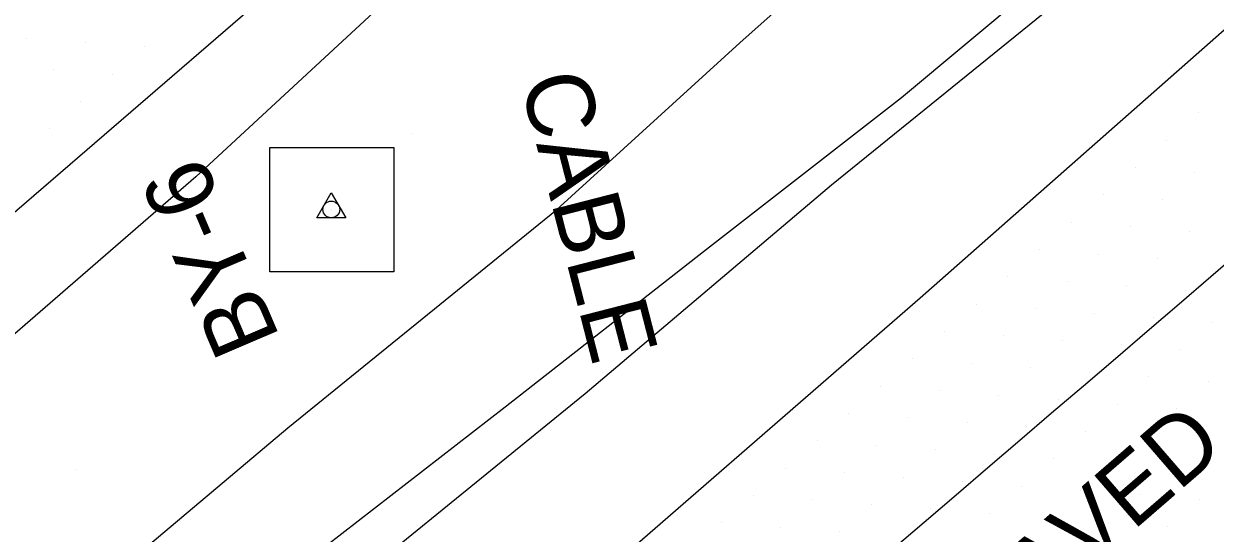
# Model space of a CAD drawing. Extents: x 1548934 to 1561348, y 809680 to 824075.
# Drawn here: x 1551686.9 to 1551757.9, y 810616.2 to 810646.5 of the extents above; entities that cross this region are included whole.
import ezdxf

# ---------------------------------------------------------------- set-up
doc = ezdxf.new("R2010")
doc.units = 0
for name, color, linetype in [('CTL Secondary Horizontal and Vertical Text', 7, 'Continuous'), ('E_NCDOT_Vertical_Profile_Ground_Line', 7, 'Continuous'), ('Exist DTM QL2 LIDAR Elevation Point', 7, 'Continuous'), ('Exist DTM Scan Elevation Point', 7, 'Continuous'), ('Exist Guardrail Cable Guide Rail', 7, 'Continuous'), ('Exist Guardrail Text', 7, 'Continuous'), ('Exist Roads EOP Text', 7, 'Continuous'), ('P_NCDOT_Horizontal_Alignment', 7, 'Continuous'), ('P_NCDOT_Horizontal_Alignment_Tick_Small', 7, 'Continuous'), ('P_RDY_Terminator_Cell', 7, 'Continuous'), ('PH Exist DTM Breakline', 7, 'Continuous')]:
    doc.layers.add(name, color=color, linetype=linetype)

msp = doc.modelspace()

# ---------------------------------------------------------------- linework, layer by layer
at = {"layer": 'E_NCDOT_Vertical_Profile_Ground_Line'}
for points in [[(1551616.71, 810576.292), (1551639.811, 810595.486), (1551662.662, 810614.925), (1551685.424, 810634.556), (1551708.169, 810654.186)], [(1551626.097, 810533.004), (1551648.898, 810552.5), (1551671.875, 810571.791), (1551694.667, 810591.296), (1551717.688, 810610.535), (1551740.33, 810630.215), (1551762.82, 810650.073)]]:
    msp.add_lwpolyline(points, dxfattribs=at)
at = {"layer": 'Exist DTM QL2 LIDAR Elevation Point'}
for p, q in [((1551709.996, 810639.982), (1551709.996, 810639.982)), ((1551699.995, 810629.981), (1551699.995, 810629.981)), ((1551689.994, 810619.98), (1551689.994, 810619.98))]:
    msp.add_line(p, q, dxfattribs=at)
at = {"layer": 'Exist DTM Scan Elevation Point'}
for p, q in [((1551687.025, 810645.703), (1551687.025, 810645.703)), ((1551690.551, 810645.436), (1551690.551, 810645.436)), ((1551694.077, 810645.169), (1551694.077, 810645.169)), ((1551688.655, 810643.807), (1551688.655, 810643.807)), ((1551692.18, 810643.54), (1551692.18, 810643.54)), ((1551690.284, 810641.911), (1551690.284, 810641.911)), ((1551756.933, 810641.237), (1551756.933, 810641.237)), ((1551688.388, 810640.282), (1551688.388, 810640.282)), ((1551755.036, 810639.607), (1551755.036, 810639.607)), ((1551753.139, 810637.978), (1551753.139, 810637.978)), ((1551756.664, 810637.71), (1551756.664, 810637.71)), ((1551751.243, 810636.349), (1551751.243, 810636.349)), ((1551754.768, 810636.081), (1551754.768, 810636.081)), ((1551749.346, 810634.72), (1551749.346, 810634.72)), ((1551752.871, 810634.452), (1551752.871, 810634.452)), ((1551756.396, 810634.184), (1551756.396, 810634.184)), ((1551747.451, 810633.092), (1551747.451, 810633.092)), ((1551750.975, 810632.823), (1551750.975, 810632.823)), ((1551754.5, 810632.555), (1551754.5, 810632.555)), ((1551745.554, 810631.463), (1551745.554, 810631.463)), ((1551749.079, 810631.195), (1551749.079, 810631.195)), ((1551752.603, 810630.927), (1551752.603, 810630.927)), ((1551756.128, 810630.659), (1551756.128, 810630.659)), ((1551743.658, 810629.834), (1551743.658, 810629.834)), ((1551747.183, 810629.566), (1551747.183, 810629.566)), ((1551750.707, 810629.298), (1551750.707, 810629.298)), ((1551754.232, 810629.03), (1551754.232, 810629.03)), ((1551757.757, 810628.762), (1551757.757, 810628.762)), ((1551741.762, 810628.205), (1551741.762, 810628.205)), ((1551745.286, 810627.937), (1551745.286, 810627.937)), ((1551748.811, 810627.669), (1551748.811, 810627.669)), ((1551752.336, 810627.401), (1551752.336, 810627.401)), ((1551755.861, 810627.133), (1551755.861, 810627.133)), ((1551739.865, 810626.576), (1551739.865, 810626.576)), ((1551743.39, 810626.308), (1551743.39, 810626.308)), ((1551746.915, 810626.04), (1551746.915, 810626.04)), ((1551750.439, 810625.772), (1551750.439, 810625.772)), ((1551753.964, 810625.504), (1551753.964, 810625.504)), ((1551737.969, 810624.947), (1551737.969, 810624.947)), ((1551741.494, 810624.679), (1551741.494, 810624.679)), ((1551757.489, 810625.236), (1551757.489, 810625.236)), ((1551745.018, 810624.411), (1551745.018, 810624.411)), ((1551748.543, 810624.143), (1551748.543, 810624.143)), ((1551736.073, 810623.319), (1551736.073, 810623.319)), ((1551752.068, 810623.875), (1551752.068, 810623.875)), ((1551755.593, 810623.607), (1551755.593, 810623.607)), ((1551739.597, 810623.05), (1551739.597, 810623.05)), ((1551743.122, 810622.782), (1551743.122, 810622.782)), ((1551746.647, 810622.514), (1551746.647, 810622.514)), ((1551750.171, 810622.246), (1551750.171, 810622.246)), ((1551753.696, 810621.978), (1551753.696, 810621.978)), ((1551734.176, 810621.69), (1551734.176, 810621.69)), ((1551737.701, 810621.422), (1551737.701, 810621.422)), ((1551741.226, 810621.153), (1551741.226, 810621.153)), ((1551757.222, 810621.711), (1551757.222, 810621.711)), ((1551744.75, 810620.885), (1551744.75, 810620.885)), ((1551748.275, 810620.617), (1551748.275, 810620.617)), ((1551732.28, 810620.061), (1551732.28, 810620.061)), ((1551735.805, 810619.793), (1551735.805, 810619.793)), ((1551751.8, 810620.35), (1551751.8, 810620.35)), ((1551755.325, 810620.082), (1551755.325, 810620.082)), ((1551739.329, 810619.524), (1551739.329, 810619.524)), ((1551742.854, 810619.256), (1551742.854, 810619.256)), ((1551746.379, 810618.988), (1551746.379, 810618.988)), ((1551730.384, 810618.432), (1551730.384, 810618.432)), ((1551749.904, 810618.721), (1551749.904, 810618.721)), ((1551753.429, 810618.453), (1551753.429, 810618.453)), ((1551733.908, 810618.164), (1551733.908, 810618.164)), ((1551737.433, 810617.896), (1551737.433, 810617.896)), ((1551740.958, 810617.628), (1551740.958, 810617.628)), ((1551756.954, 810618.185), (1551756.954, 810618.185)), ((1551744.482, 810617.36), (1551744.482, 810617.36)), ((1551748.007, 810617.092), (1551748.007, 810617.092)), ((1551728.487, 810616.803), (1551728.487, 810616.803)), ((1551732.012, 810616.535), (1551732.012, 810616.535)), ((1551735.536, 810616.267), (1551735.536, 810616.267)), ((1551751.533, 810616.824), (1551751.533, 810616.824)), ((1551755.058, 810616.556), (1551755.058, 810616.556))]:
    msp.add_line(p, q, dxfattribs=at)
at = {"layer": 'Exist Guardrail Cable Guide Rail'}
msp.add_lwpolyline([(1551762.322, 810661.326), (1551750.708, 810651.754), (1551739.198, 810642.126), (1551727.399, 810632.951), (1551715.572, 810623.694), (1551703.898, 810614.617), (1551692.087, 810605.359), (1551680.215, 810595.939), (1551668.418, 810586.655), (1551656.719, 810577.461), (1551645.067, 810568.012), (1551633.432, 810558.34)], dxfattribs=at)
at = {"layer": 'P_NCDOT_Horizontal_Alignment'}
msp.add_line((1551705.209, 810635.48), (1551705.209, 810635.48), dxfattribs=at)
msp.add_line((1551705.209, 810635.48), (1551705.209, 810635.48), dxfattribs=at)
msp.add_lwpolyline([(1551704.343, 810634.98), (1551705.209, 810636.48), (1551706.075, 810634.98)], close=True, dxfattribs=at)
msp.add_lwpolyline([(1551704.343, 810634.98), (1551705.209, 810636.48), (1551706.075, 810634.98)], close=True, dxfattribs=at)
msp.add_circle((1551705.209, 810635.48), 0.5, dxfattribs=at)
msp.add_circle((1551705.209, 810635.48), 0.5, dxfattribs=at)
at = {"layer": 'P_NCDOT_Horizontal_Alignment_Tick_Small'}
msp.add_line((1551705.209, 810635.48), (1551705.209, 810635.48), dxfattribs=at)
msp.add_line((1551705.209, 810635.48), (1551705.209, 810635.48), dxfattribs=at)
msp.add_lwpolyline([(1551701.534, 810639.18), (1551708.946, 810639.18), (1551708.946, 810631.755), (1551701.534, 810631.755)], close=True, dxfattribs=at)
msp.add_lwpolyline([(1551701.534, 810639.18), (1551708.946, 810639.18), (1551708.946, 810631.755), (1551701.534, 810631.755)], close=True, dxfattribs=at)
at = {"layer": 'P_RDY_Terminator_Cell'}
msp.add_lwpolyline([(1551738.663, 810615.215), (1551740.562, 810616.84), (1551742.462, 810618.466), (1551744.361, 810620.092), (1551746.26, 810621.717), (1551748.16, 810623.343), (1551750.059, 810624.968), (1551751.958, 810626.594), (1551753.857, 810628.22), (1551755.757, 810629.845), (1551757.655, 810631.472), (1551759.54, 810633.114)], dxfattribs=at)
at = {"layer": 'PH Exist DTM Breakline'}
for points in [[(1551782.675, 810715.1), (1551773.007, 810705.306), (1551748.224, 810683.207), (1551726.249, 810664.382), (1551697.139, 810637.424), (1551676.304, 810619.385), (1551647.753, 810594.047)], [(1551651.205, 810580.522), (1551687.185, 810609.458), (1551702.625, 810622.447), (1551718.628, 810635.449), (1551729.562, 810645.41), (1551739.115, 810653.932), (1551744.683, 810656.108), (1551750.431, 810659.106), (1551762.96, 810666.985), (1551775.458, 810674.948), (1551786.415, 810682.456), (1551796.394, 810690.846), (1551801.831, 810695.248), (1551805.641, 810698.006)], [(1551653.907, 810568.703), (1551685.171, 810595.198), (1551701.493, 810609.165), (1551720.353, 810624.512), (1551735.042, 810636.95), (1551753.182, 810651.66), (1551776.02, 810668.331), (1551786.005, 810676.439), (1551801.211, 810689.818), (1551806.098, 810694.152)]]:
    msp.add_lwpolyline(points, dxfattribs=at)

# ---------------------------------------------------------------- texts
at = {"layer": 'CTL Secondary Horizontal and Vertical Text'}
msp.add_text('BY-6', height=4.02, rotation=113.16136, dxfattribs=at).set_placement((1551702.175, 810627.824))
at = {"layer": 'Exist Guardrail Text'}
msp.add_text('CABLE', height=4.02, rotation=284.4207, dxfattribs=at).set_placement((1551716.447, 810643.155))
at = {"layer": 'Exist Roads EOP Text'}
msp.add_text("I-40 EB 45' PAVED", height=4.02, rotation=40.88002, dxfattribs=at).set_placement((1551723.764, 810590.969))

doc.saveas('drawing.dxf')
